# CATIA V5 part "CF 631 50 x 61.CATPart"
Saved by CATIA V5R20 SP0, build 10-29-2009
Part number: CF 631 50 x 61
Definition: NONE
Nomenclature: CF 631 50 x 61
Source: Unknown
Description: CF 631 50 x 61
Bounding box of the stored display mesh (mm): x -13 to 48, y -39.5 to 39.5, z -39.5 to 39.5
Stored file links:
  C:\Users\Utente\Desktop\IO LAVORO\3D X SITO CF\X SITO\CF 631\CF 631 50 x 61.CATPart
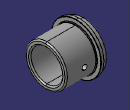
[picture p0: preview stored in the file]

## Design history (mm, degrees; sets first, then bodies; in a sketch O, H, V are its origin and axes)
Body1 "CF 631 50 x 61" (main body)
  Solid1: solid without history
